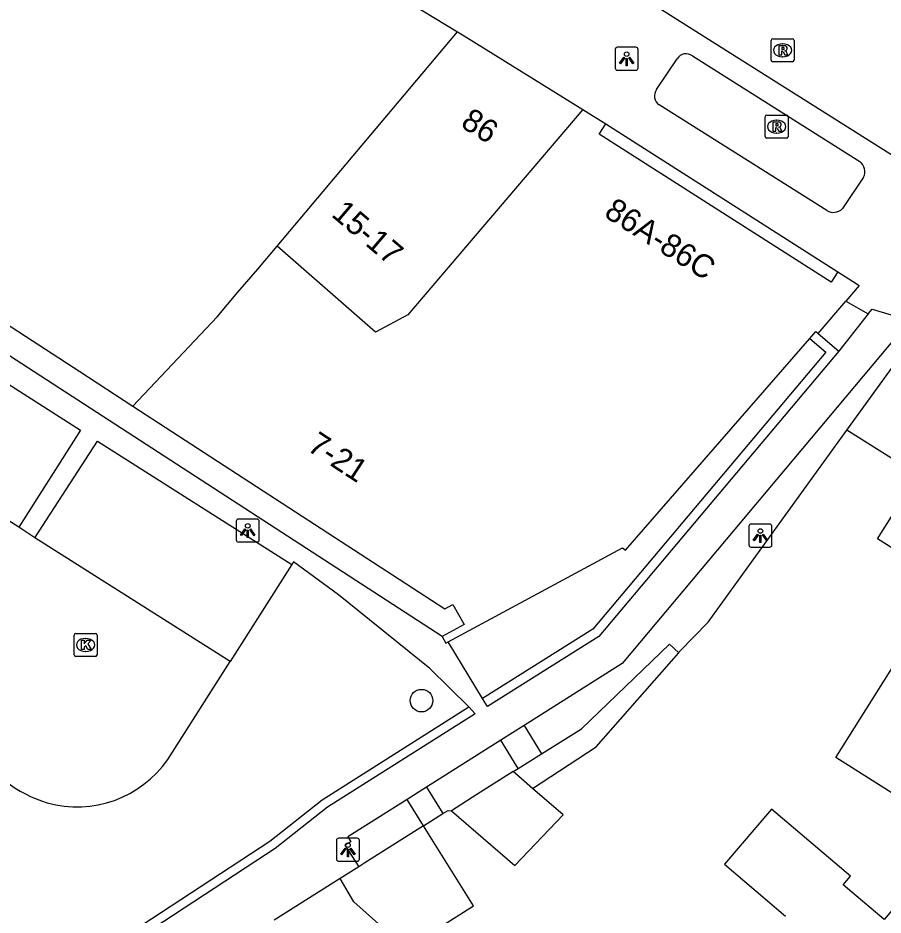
# Model space of a CAD drawing. Extents: x 161801 to 162379, y 382315 to 382832.
# Drawn here: x 162087.53 to 162125.06, y 382637.32 to 382676.21 of the extents above; entities that cross this region are included whole.
import ezdxf

# ---------------------------------------------------------------- set-up
doc = ezdxf.new("R2010")
doc.units = 0
for name, color, linetype in [('IMGEO_Boom', 7, 'Continuous'), ('IMGEO_Grasland_overig', 7, 'Continuous'), ('IMGEO_Groenvoorziening', 7, 'Continuous'), ('IMGEO_Haag', 7, 'Continuous'), ('IMGEO_Kolk', 7, 'Continuous'), ('IMGEO_Lichtpunt', 7, 'Continuous'), ('IMGEO_Pand', 7, 'Continuous'), ('IMGEO_Pand_nummerreeks', 7, 'Continuous'), ('IMGEO_Parkeervlak_open', 7, 'Continuous'), ('IMGEO_Rijbaan_lokaal_open', 7, 'Continuous'), ('IMGEO_Rioolput', 7, 'Continuous'), ('IMGEO_Voetpad_open', 7, 'Continuous')]:
    doc.layers.add(name, color=color, linetype=linetype)

msp = doc.modelspace()

# ---------------------------------------------------------------- linework, layer by layer
at = {"layer": 'IMGEO_Boom'}
msp.add_circle((162105.036, 382646.615), 0.489, dxfattribs=at)
at = {"layer": 'IMGEO_Grasland_overig'}
for points in [[(162110.247, 382644.31), (162111.973, 382645.388), (162115.796, 382649.068), (162116.194, 382648.694)], [(162109.858, 382642.812), (162112.62, 382644.614), (162116.194, 382648.694)], [(162109.017, 382643.539), (162109.233, 382643.677)]]:
    msp.add_lwpolyline(points, dxfattribs=at)
at = {"layer": 'IMGEO_Groenvoorziening'}
for points in [[(162116.194, 382648.694), (162116.22, 382648.724), (162116.246, 382648.753), (162117.475, 382650.02), (162123.491, 382658.338)], [(162105.967, 382641.715), (162106.191, 382641.856), (162106.339, 382641.843)]]:
    msp.add_lwpolyline(points, dxfattribs=at)
at = {"layer": 'IMGEO_Haag'}
for points in [[(162121.881, 382662.313), (162122.583, 382661.721), (162112.464, 382649.707), (162107.688, 382646.703)], [(162071.632, 382622.978), (162083.938, 382631.006), (162083.617, 382631.522), (162086.587, 382633.461), (162086.912, 382632.968), (162098.453, 382640.526), (162100.721, 382642.321), (162107.093, 382646.349)]]:
    msp.add_lwpolyline(points, dxfattribs=at)
at = {"layer": 'IMGEO_Kolk'}
for p, q in [((162089.964, 382648.604), (162089.964, 382649.456)), ((162090.039, 382649.53), (162090.891, 382649.53)), ((162090.452, 382649.31), (162090.477, 382649.31)), ((162090.965, 382649.456), (162090.965, 382648.604)), ((162090.891, 382648.53), (162090.039, 382648.53)), ((162090.475, 382648.75), (162090.45, 382648.75))]:
    msp.add_line(p, q, dxfattribs=at)
for points in [[(162089.964, 382648.604), (162089.964, 382649.456)], [(162090.039, 382649.53), (162090.891, 382649.53)], [(162090.285, 382649.23), (162090.408, 382649.23), (162090.408, 382649.079), (162090.538, 382649.23), (162090.702, 382649.23), (162090.556, 382649.079), (162090.709, 382648.83), (162090.557, 382648.83), (162090.472, 382648.994), (162090.408, 382648.927), (162090.408, 382648.83), (162090.285, 382648.83), (162090.285, 382649.23)], [(162090.965, 382649.456), (162090.965, 382648.604)], [(162090.891, 382648.53), (162090.039, 382648.53)]]:
    msp.add_lwpolyline(points, dxfattribs=at)
for centre, start, end in [((162090.041, 382649.454), 91.552, 178.448), ((162090.041, 382649.454), 91.552, 178.448), ((162090.889, 382649.454), 1.552, 88.448), ((162090.889, 382649.454), 1.552, 88.448), ((162090.041, 382648.606), 181.552, 268.448), ((162090.041, 382648.606), 181.552, 268.448), ((162090.889, 382648.606), 271.552, 358.448), ((162090.889, 382648.606), 271.552, 358.448)]:
    msp.add_arc(centre, 0.0765, start, end, dxfattribs=at)
for centre, major_axis, ratio, start_param, end_param in [((162090.451, 382649.03), (-0.387, 0.002), 0.722429, 4.712389, 7.853982), ((162090.476, 382649.03), (-0.39, 0.002), 0.717154, 1.570796, 4.712389)]:
    msp.add_ellipse(centre, major_axis=major_axis, ratio=ratio, start_param=start_param, end_param=end_param, dxfattribs=at)
at = {"layer": 'IMGEO_Lichtpunt'}
for p, q in [((162114.341, 382674.942), (162113.533, 382674.942)), ((162114.341, 382674.942), (162113.533, 382674.942)), ((162113.439, 382674.847), (162113.439, 382674.04)), ((162113.439, 382674.847), (162113.439, 382674.04)), ((162114.435, 382674.04), (162114.435, 382674.847)), ((162114.435, 382674.04), (162114.435, 382674.847)), ((162113.533, 382673.946), (162114.341, 382673.946)), ((162113.533, 382673.946), (162114.341, 382673.946)), ((162096.999, 382654.394), (162096.999, 382653.587)), ((162096.999, 382654.394), (162096.999, 382653.587)), ((162097.901, 382654.489), (162097.093, 382654.489)), ((162097.901, 382654.489), (162097.093, 382654.489)), ((162097.995, 382653.587), (162097.995, 382654.394)), ((162097.995, 382653.587), (162097.995, 382654.394)), ((162120.142, 382654.268), (162119.334, 382654.268)), ((162120.142, 382654.268), (162119.334, 382654.268)), ((162119.24, 382654.173), (162119.24, 382653.366)), ((162119.24, 382654.173), (162119.24, 382653.366)), ((162120.236, 382653.366), (162120.236, 382654.173)), ((162120.236, 382653.366), (162120.236, 382654.173)), ((162097.093, 382653.493), (162097.901, 382653.493)), ((162097.093, 382653.493), (162097.901, 382653.493)), ((162119.334, 382653.272), (162120.142, 382653.272)), ((162119.334, 382653.272), (162120.142, 382653.272)), ((162101.346, 382640.552), (162101.346, 382639.745)), ((162101.346, 382640.552), (162101.346, 382639.745)), ((162102.248, 382640.647), (162101.44, 382640.647)), ((162102.248, 382640.647), (162101.44, 382640.647)), ((162102.342, 382639.745), (162102.342, 382640.552)), ((162102.342, 382639.745), (162102.342, 382640.552)), ((162101.44, 382639.651), (162102.248, 382639.651)), ((162101.44, 382639.651), (162102.248, 382639.651))]:
    msp.add_line(p, q, dxfattribs=at)
for points in [[(162113.813, 382674.511), (162113.852, 382674.483), (162113.664, 382674.221), (162113.626, 382674.248), (162113.813, 382674.511)], [(162114.025, 382674.483), (162114.063, 382674.51), (162114.25, 382674.248), (162114.211, 382674.22), (162114.025, 382674.483)], [(162113.915, 382674.463), (162113.962, 382674.463), (162113.962, 382674.141), (162113.915, 382674.141), (162113.915, 382674.463)], [(162097.373, 382654.058), (162097.412, 382654.03), (162097.224, 382653.768), (162097.186, 382653.795), (162097.373, 382654.058)], [(162097.475, 382654.01), (162097.522, 382654.01), (162097.522, 382653.688), (162097.475, 382653.688), (162097.475, 382654.01)], [(162097.585, 382654.03), (162097.623, 382654.057), (162097.81, 382653.795), (162097.771, 382653.767), (162097.585, 382654.03)], [(162119.614, 382653.837), (162119.653, 382653.809), (162119.465, 382653.547), (162119.427, 382653.574), (162119.614, 382653.837)], [(162119.716, 382653.789), (162119.763, 382653.789), (162119.763, 382653.467), (162119.716, 382653.467), (162119.716, 382653.789)], [(162119.826, 382653.809), (162119.864, 382653.836), (162120.051, 382653.574), (162120.012, 382653.546), (162119.826, 382653.809)], [(162101.72, 382640.216), (162101.759, 382640.188), (162101.571, 382639.926), (162101.533, 382639.953), (162101.72, 382640.216)], [(162101.822, 382640.168), (162101.869, 382640.168), (162101.869, 382639.846), (162101.822, 382639.846), (162101.822, 382640.168)], [(162101.932, 382640.188), (162101.97, 382640.215), (162102.157, 382639.953), (162102.118, 382639.925), (162101.932, 382640.188)]]:
    msp.add_lwpolyline(points, dxfattribs=at)
for centre in [(162113.938, 382674.645), (162097.498, 382654.192), (162119.739, 382653.971), (162101.845, 382640.35)]:
    msp.add_circle(centre, 0.0994, dxfattribs=at)
for centre, start, end in [((162113.533, 382674.847), 90, 180), ((162113.533, 382674.847), 90, 180), ((162114.341, 382674.847), 0, 90), ((162114.341, 382674.847), 0, 90), ((162113.533, 382674.04), 180, 270), ((162113.533, 382674.04), 180, 270), ((162114.341, 382674.04), 270, 0), ((162114.341, 382674.04), 270, 360), ((162097.093, 382654.394), 90, 180), ((162097.093, 382654.394), 90, 180), ((162097.901, 382654.394), 0, 90), ((162097.901, 382654.394), 0, 90), ((162119.334, 382654.173), 90, 180), ((162119.334, 382654.173), 90, 180), ((162120.142, 382654.173), 0, 90), ((162120.142, 382654.173), 0, 90), ((162097.093, 382653.587), 180, 270), ((162097.093, 382653.587), 180, 270), ((162097.901, 382653.587), 270, 0), ((162097.901, 382653.587), 270, 360), ((162119.334, 382653.366), 180, 270), ((162119.334, 382653.366), 180, 270), ((162120.142, 382653.366), 270, 0), ((162120.142, 382653.366), 270, 360), ((162101.44, 382640.552), 90, 180), ((162101.44, 382640.552), 90, 180), ((162102.248, 382640.552), 0, 90), ((162102.248, 382640.552), 0, 90), ((162101.44, 382639.745), 180, 270), ((162101.44, 382639.745), 180, 270), ((162102.248, 382639.745), 270, 0), ((162102.248, 382639.745), 270, 360)]:
    msp.add_arc(centre, 0.0946, start, end, dxfattribs=at)
at = {"layer": 'IMGEO_Pand'}
for points in [[(162087.494, 382688.013), (162103.949, 382677.238), (162104.136, 382677.116), (162106.594, 382675.618)], [(162098.773, 382666.323), (162106.594, 382675.618)], [(162106.594, 382675.618), (162106.889, 382675.435), (162112.042, 382672.242)], [(162112.042, 382672.242), (162104.436, 382663.341), (162103.042, 382662.591), (162098.773, 382666.323)], [(162112.042, 382672.242), (162113.034, 382671.627)], [(162072.703, 382670.936), (162073.412, 382672.036), (162074.251, 382671.491), (162074.142, 382671.323), (162090.218, 382660.88), (162092.518, 382659.386)], [(162123.097, 382665.212), (162122.807, 382664.757), (162112.749, 382671.175), (162113.034, 382671.627)], [(162092.518, 382659.386), (162094.953, 382661.964), (162096.171, 382663.253), (162097.075, 382664.32), (162097.929, 382665.328), (162098.773, 382666.323)], [(162123.097, 382665.212), (162123.733, 382664.808), (162124.03, 382664.619), (162123.446, 382663.939)], [(162122.238, 382662.535), (162123.446, 382663.939)], [(162121.881, 382662.313), (162122.144, 382662.616), (162122.238, 382662.535)], [(162106.192, 382649.16), (162113.749, 382653.246), (162113.889, 382653.134), (162121.881, 382662.313)], [(162123.491, 382658.338), (162126.268, 382662.17)], [(162092.518, 382659.386), (162106.053, 382650.594), (162106.401, 382650.789), (162106.885, 382649.914), (162105.935, 382649.39)], [(162125.839, 382642.364), (162123.01, 382644.148), (162127.804, 382651.749), (162124.821, 382653.63), (162126.567, 382656.399), (162123.491, 382658.338)], [(162105.935, 382649.39), (162106.092, 382649.106), (162106.192, 382649.16)], [(162109.017, 382643.539), (162107.44, 382642.541), (162106.339, 382641.843)], [(162109.858, 382642.812), (162109.017, 382643.539)], [(162106.339, 382641.843), (162109.091, 382639.464), (162111.188, 382641.663), (162109.858, 382642.812)], [(162133.856, 382634.079), (162127.271, 382639.672), (162125.102, 382637.119), (162123.327, 382638.627), (162123.644, 382639.001), (162120.214, 382641.914), (162118.181, 382639.521), (162120.834, 382637.267)], [(162105.117, 382641.18), (162102.578, 382639.58), (162102.314, 382639.414)], [(162104.377, 382635.872), (162107.299, 382637.712), (162105.117, 382641.18)], [(162102.314, 382639.414), (162101.503, 382638.903)], [(162101.503, 382638.903), (162098.642, 382637.101)], [(162104.377, 382635.872), (162102.104, 382637.898), (162101.503, 382638.903)]]:
    msp.add_lwpolyline(points, dxfattribs=at)
at = {"layer": 'IMGEO_Parkeervlak_open'}
msp.add_lwpolyline([(162099.415, 382652.521), (162096.732, 382648.306)], dxfattribs=at)
at = {"layer": 'IMGEO_Rijbaan_lokaal_open'}
for points in [[(162099.27, 382686.974), (162103.542, 382684.136), (162109.115, 382680.594), (162117.092, 382675.543), (162129.893, 382667.475), (162130.048, 382667.707)], [(162087.562, 382654.137), (162076.445, 382661.19)], [(162088.266, 382653.675), (162087.562, 382654.137)], [(162096.732, 382648.306), (162088.266, 382653.675)], [(162094.025, 382644.065), (162096.732, 382648.306)]]:
    msp.add_lwpolyline(points, dxfattribs=at)
for centre, radius, start, end in [((162090.469, 382647.611), 5.679, 211.6895, 252.8725), ((162090.091, 382646.793), 4.787, 254.3063, 325.2635)]:
    msp.add_arc(centre, radius, start, end, dxfattribs=at)
at = {"layer": 'IMGEO_Rioolput'}
for p, q in [((162120.277, 382675.312), (162121.129, 382675.312)), ((162120.202, 382674.386), (162120.202, 382675.238)), ((162120.69, 382675.092), (162120.715, 382675.092)), ((162121.203, 382675.238), (162121.203, 382674.386)), ((162120.713, 382674.532), (162120.688, 382674.532)), ((162121.129, 382674.312), (162120.277, 382674.312)), ((162119.943, 382671.077), (162119.943, 382671.929)), ((162120.018, 382672.003), (162120.87, 382672.003)), ((162120.431, 382671.783), (162120.456, 382671.783)), ((162120.944, 382671.929), (162120.944, 382671.077)), ((162120.87, 382671.003), (162120.018, 382671.003)), ((162120.454, 382671.223), (162120.429, 382671.223))]:
    msp.add_line(p, q, dxfattribs=at)
for points in [[(162120.277, 382675.312), (162121.129, 382675.312)], [(162120.202, 382674.386), (162120.202, 382675.238)], [(162120.791, 382675.01), (162120.539, 382675.012), (162120.539, 382674.612)], [(162120.717, 382674.931), (162120.663, 382674.931), (162120.663, 382674.85)], [(162121.203, 382675.238), (162121.203, 382674.386)], [(162120.539, 382674.612), (162120.663, 382674.612), (162120.663, 382674.774), (162120.674, 382674.774)], [(162120.663, 382674.85), (162120.715, 382674.85)], [(162120.721, 382674.745), (162120.792, 382674.612), (162120.932, 382674.612), (162120.867, 382674.738)], [(162121.129, 382674.312), (162120.277, 382674.312)], [(162119.943, 382671.077), (162119.943, 382671.929)], [(162120.018, 382672.003), (162120.87, 382672.003)], [(162120.944, 382671.929), (162120.944, 382671.077)], [(162120.532, 382671.701), (162120.28, 382671.703), (162120.28, 382671.303)], [(162120.28, 382671.303), (162120.404, 382671.303), (162120.404, 382671.465), (162120.415, 382671.465)], [(162120.458, 382671.622), (162120.404, 382671.622), (162120.404, 382671.541)], [(162120.404, 382671.541), (162120.456, 382671.541)], [(162120.462, 382671.436), (162120.533, 382671.303), (162120.673, 382671.303), (162120.608, 382671.429)], [(162120.87, 382671.003), (162120.018, 382671.003)]]:
    msp.add_lwpolyline(points, dxfattribs=at)
for centre, radius, start, end in [((162120.279, 382675.236), 0.0765, 91.552, 178.448), ((162120.279, 382675.236), 0.0765, 91.552, 178.448), ((162121.127, 382675.236), 0.0765, 1.552, 88.448), ((162121.127, 382675.236), 0.0765, 1.552, 88.448), ((162120.723, 382674.835), 0.0964, 77.0061, 93.1865), ((162120.737, 382674.892), 0.0378, 276.6634, 79.6772), ((162120.79, 382674.9), 0.109, 350.3612, 89.416), ((162120.673, 382674.721), 0.0533, 26.0293, 88.6989), ((162120.699, 382675.039), 0.19, 274.7715, 282.9687), ((162120.788, 382674.9), 0.112, 277.5842, 350.9817), ((162120.772, 382674.685), 0.108, 29.5134, 73.7905), ((162120.279, 382674.388), 0.0765, 181.552, 268.448), ((162120.279, 382674.388), 0.0765, 181.552, 268.448), ((162121.127, 382674.388), 0.0765, 271.552, 358.448), ((162121.127, 382674.388), 0.0765, 271.552, 358.448), ((162120.02, 382671.927), 0.0765, 91.552, 178.448), ((162120.02, 382671.927), 0.0765, 91.552, 178.448), ((162120.868, 382671.927), 0.0765, 1.552, 88.448), ((162120.868, 382671.927), 0.0765, 1.552, 88.448), ((162120.414, 382671.412), 0.0533, 26.0293, 88.6989), ((162120.44, 382671.73), 0.19, 274.7715, 282.9687), ((162120.464, 382671.526), 0.0964, 77.0061, 93.1865), ((162120.478, 382671.583), 0.0378, 276.6634, 79.6772), ((162120.531, 382671.591), 0.109, 350.3612, 89.416), ((162120.529, 382671.591), 0.112, 277.5842, 350.9817), ((162120.513, 382671.376), 0.108, 29.5134, 73.7905), ((162120.02, 382671.079), 0.0765, 181.552, 268.448), ((162120.02, 382671.079), 0.0765, 181.552, 268.448), ((162120.868, 382671.079), 0.0765, 271.552, 358.448), ((162120.868, 382671.079), 0.0765, 271.552, 358.448)]:
    msp.add_arc(centre, radius, start, end, dxfattribs=at)
for centre, major_axis, ratio, start_param, end_param in [((162120.689, 382674.812), (-0.387, 0.002), 0.722429, 4.712389, 7.853982), ((162120.714, 382674.812), (-0.39, 0.002), 0.717154, 1.570796, 4.712389), ((162120.43, 382671.503), (-0.387, 0.002), 0.722429, 4.712389, 7.853982), ((162120.455, 382671.503), (-0.39, 0.002), 0.717154, 1.570796, 4.712389)]:
    msp.add_ellipse(centre, major_axis=major_axis, ratio=ratio, start_param=start_param, end_param=end_param, dxfattribs=at)
at = {"layer": 'IMGEO_Voetpad_open'}
for points in [[(162116.792, 382674.572), (162124.054, 382669.986)], [(162115.23, 382673.109), (162116.129, 382674.443)], [(162122.621, 382667.865), (162115.353, 382672.454)], [(162113.034, 382671.627), (162123.097, 382665.212)], [(162105.935, 382649.39), (162072.703, 382670.936)], [(162124.212, 382669.308), (162123.295, 382667.949)], [(162076.445, 382661.19), (162079.125, 382665.431), (162090.247, 382658.342), (162087.562, 382654.137)], [(162123.446, 382663.939), (162124.415, 382663.379)], [(162124.415, 382663.379), (162123.146, 382661.769)], [(162124.415, 382663.379), (162124.583, 382663.586), (162126.232, 382663.098), (162125.705, 382662.471)], [(162125.705, 382662.471), (162113.737, 382648.232), (162109.486, 382645.543)], [(162122.238, 382662.535), (162123.146, 382661.769)], [(162123.146, 382661.769), (162112.73, 382649.402), (162107.896, 382646.361), (162107.688, 382646.703)], [(162088.266, 382653.675), (162090.982, 382657.86), (162099.415, 382652.521)], [(162107.093, 382646.349), (162105.404, 382648.013), (162101.431, 382651.203), (162099.476, 382652.633), (162099.415, 382652.521)], [(162107.688, 382646.703), (162106.192, 382649.16)], [(162107.093, 382646.349), (162107.365, 382646.048), (162100.953, 382641.994), (162098.687, 382640.201), (162086.798, 382632.415), (162086.472, 382632.908), (162084.164, 382631.401), (162084.484, 382630.885), (162071.854, 382622.645), (162071.632, 382622.978)], [(162109.486, 382645.543), (162108.478, 382644.905)], [(162109.486, 382645.543), (162110.247, 382644.31)], [(162108.478, 382644.905), (162105.252, 382642.865)], [(162109.233, 382643.677), (162108.478, 382644.905)], [(162109.233, 382643.677), (162110.247, 382644.31)], [(162105.252, 382642.865), (162104.411, 382642.333)], [(162105.252, 382642.865), (162105.967, 382641.715)], [(162104.411, 382642.333), (162101.838, 382640.705), (162101.969, 382640.49), (162101.713, 382640.345), (162102.314, 382639.414)], [(162105.117, 382641.18), (162104.411, 382642.333)], [(162105.117, 382641.18), (162105.967, 382641.715)]]:
    msp.add_lwpolyline(points, dxfattribs=at)
for centre, radius, start, end in [((162116.519, 382674.209), 0.454, 52.9997, 149.0212), ((162115.593, 382672.838), 0.453, 143.2787, 237.9923), ((162123.734, 382669.554), 0.538, 332.7951, 53.4409), ((162122.906, 382668.325), 0.541, 238.2192, 315.989)]:
    msp.add_arc(centre, radius, start, end, dxfattribs=at)

# ---------------------------------------------------------------- texts
at = {"layer": 'IMGEO_Pand_nummerreeks'}
for s, rotation, p in [('86', 327.6211, (162106.684, 382671.523)), ('86A-86C', 327.6852, (162112.906, 382667.629)), ('15-17', 319.5958, (162101.083, 382667.644)), ('7-21', 326.7799, (162100.025, 382657.497))]:
    msp.add_text(s, height=1, rotation=rotation, dxfattribs=at).set_placement(p)

doc.saveas('drawing.dxf')
